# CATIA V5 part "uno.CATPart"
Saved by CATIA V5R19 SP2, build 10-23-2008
Part number: uno
Revision: ANY
Definition: UNKNOWN
Nomenclature: uno
Source: Unknown
Bounding box of the stored display mesh (mm): x -7 to 68, y 0 to 12.6, z -53 to 0
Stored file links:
  Z:\charly_robot\uno.CATPart
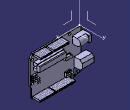
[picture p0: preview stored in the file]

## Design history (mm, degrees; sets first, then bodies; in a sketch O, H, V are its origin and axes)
AxisSystem1: origin (0, 0, 0), X (1, 0, 0), Y (0, 1, 0), Z (0, 0, 1)
Body1 "Chamfer1" (main body)
  Solid1: solid without history
Body2 "Fillet1"
  Solid2: solid without history
Body3 "Boss-Extrude4[1]"
  Solid3: solid without history
Body4 "Boss-Extrude4[2]"
  Solid4: solid without history
Body5 "Boss-Extrude4[3]"
  Solid5: solid without history
Body6 "Boss-Extrude4[4]"
  Solid6: solid without history
Body7 "Cut-Extrude4"
  Solid7: solid without history
Body8 "Chamfer2"
  Solid8: solid without history
Body9 "Boss-Extrude12"
  Solid9: solid without history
